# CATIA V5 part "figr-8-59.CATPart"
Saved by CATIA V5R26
Part number: Part1
Bounding box of the stored display mesh (mm): x -50.499 to 50.499, y -68.48 to 68.48, z -50 to 50
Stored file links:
  D:\_Deepak\CATIA\CATIA V5-6R2016_Deepak\Resources\Part files\Partfiles\c08_catia_v5_6r2016_prt\figr-8-59.CATPart
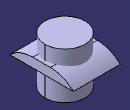
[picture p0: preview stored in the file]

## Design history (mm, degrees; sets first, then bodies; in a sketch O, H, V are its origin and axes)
Body1 (main body)
  Sketch1 on xy-plane, origin (0, 0, 0), H (1, 0, 0), V (0, 1, 0)
    line L1 (-50.499, 68.4797) -> (50.499, 68.4797)
    line L2 (50.499, 68.4797) -> (50.499, -68.4797)
    line L3 (50.499, -68.4797) -> (-50.499, -68.4797)
    line L4 (-50.499, -68.4797) -> (-50.499, 68.4797)
    axis line L5 (50.499, -68.4797) -> (-50.499, 68.4797)
    horizontal: L1 H, L3 H
    vertical: L2 V, L4 V
    midpoint: O L5
  Pad1: profile Sketch1, direction (0, 0, 1), length 20
  Fillet1: radius 71, on edge [face of Pad1 | face of Pad1]
  Fillet2: radius 71, on edge [face of Pad1 | face of Pad1]
Body2
  Sketch2 on xy-plane, origin (0, 0, 0), H (1, 0, 0), V (0, 1, 0)
    circle A1 centre (0, 0) radius 43.2524
    point P1 (0, 43.2524)
    coincidence: A1 P1, P1 V
  Pocket1: profile Sketch2, direction (0, 0, -1), length 50, mirrored extent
